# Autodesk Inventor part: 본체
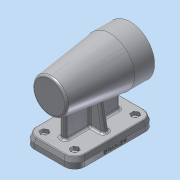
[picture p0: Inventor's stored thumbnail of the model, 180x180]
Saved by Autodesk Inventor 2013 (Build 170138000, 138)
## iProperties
Created: 2017-01
Part Number: 본체
Material: 알루미늄 6061
Document SubType Name: Modeling
Designer: dgall
Density: 1 g/cm^3
Author: dgall
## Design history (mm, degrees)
sketch "스케치1"
  geometry: C1 r 34 at (0, 0); 1 further point
  constraints: 1 centre point, 1 coincident
  dimensions: "d0" = 68 diameter of C1
extrude "돌출1" new body sketch "스케치1" distance "d2" = 28; taper "d3" = 0 deg
sketch "스케치2"
  geometry: C1 r 34 at (0, 0) reference; C2 r 34 at (0, 0)
  constraints: 1 centre point, 1 coincident, 1 concentric
extrude "돌출2" join sketch "스케치2" distance "d4" = 84; taper "d5" = -7 deg
node "작업 평면1"
sketch "스케치3"
  geometry: L1 (-35, -84)-(35, -84); L2 (35, -84)-(35, 28); L3 (35, 28)-(-35, 28); L4 (-35, 28)-(-35, -84); L5 (-34, 0)-(-23.686, -84) reference; L6 (-34, 0)-(-34, 28) reference; L7 (-30.562, -28)-(-14.801, -28); L8 (23.686, -84)-(-23.686, -84) reference; L9 (0, -84)-(0, -66.42); 1 further point
  constraints: 12 end point, 3 perpendicular, 2 parallel, 1 horizontal, 1 midpoint, 1 point on line
  dimensions: "d7" = 56 vertical distance of L7.start L5.end; "d8" = 56 distance between parallel lines of L1 L7; "d9" = 56 distance between parallel lines of L3 L7; "d10" = 35 distance between parallel lines of L4 L9; "d11" = 35 distance between parallel lines of L9 L2
extrude "돌출3" join sketch "스케치3" distance "d12" = 7; taper "d13" = 0 deg
sketch "스케치4"
  geometry: L1 (-35, -84)-(35, -84) reference; L2 (35, -84)-(35, 28) reference; L3 (35, 28)-(-35, 28) reference; L4 (-35, -84)-(35, -84); L5 (35, -84)-(35, 28); L6 (35, 28)-(-35, 28); L7 (-35, 28)-(-35, -84); 1 further point
  constraints: 8 end point, 2 parallel, 1 horizontal, 1 perpendicular, 1 point on line
  dimensions: "d14" = 0 distance between parallel lines of L3 L6
extrude "돌출4" join sketch "스케치4" distance "d15" = 7; taper "d16" = -15 deg
node "작업 평면2"
sketch "스케치5"
  geometry: L1 (-82.124, -60)-(26.124, -60) reference; L2 (0, -34)-(-84, -23.686) reference; L3 (0, -34)-(28, -34) reference; L4 (-66, -25.896)-(-66, -60); L5 (-84, -74)-(-84, -67) reference; L6 (10, -34)-(10, -60); L7 (28, -74)-(28, -67) reference; L8 (-66, -60)-(10, -60); L9 (-66, -25.896)-(0, -34); L10 (10, -34)-(0, -34); 1 further point
  constraints: 10 end point, 4 point on line, 3 collinear, 2 perpendicular
  dimensions: "d18" = 18 distance from line of L4.end L5; "d19" = 18 distance from line of L6.end L7
extrude "돌출5" join sketch "스케치5" stored distance "d20" = 8; taper "d21" = 0 deg
node "작업 평면3"
sketch "스케치6"
  geometry: L1 (-33.124, -60)-(33.124, -60) reference; L2 (-23, -60)-(-17.555, -29.118); L3 (-35, -74)-(-35, -67) reference; 2 further points
  constraints: 2 end point, 1 point on line
  dimensions: "d23" = 12 distance from line of L2.start L3; "d24" = 100 deg angle of L1 L2
sketch "스케치7"
  geometry: C1 r 34 at (0, 0) reference; C2 r 21 at (0, 0)
  constraints: 1 centre point, 1 coincident
  dimensions: "d25" = 42 diameter of C2
extrude "돌출6" cut sketch "스케치7" distance "d27" = 15; taper "d28" = 0 deg
sketch "스케치8"
  geometry: C1 r 21 at (0, 0) reference; C2 r 24 at (0, 0)
  constraints: 1 centre point, 1 coincident
  dimensions: "d29" = 48 diameter of C2
extrude "돌출7" cut sketch "스케치8" distance "d31" = 54; taper "d32" = 0 deg
sketch "스케치9"
  geometry: C1 r 21 at (0, 0) reference
extrude "돌출8" cut sketch "스케치9" distance "d33" = 54; taper "d34" = 0 deg
sketch "스케치10"
  geometry: C1 r 24 at (0, 0) reference; C2 r 21 at (0, 0)
  constraints: 1 centre point, 1 coincident
  dimensions: "d35" = 42 diameter of C2
extrude "돌출9" cut sketch "스케치10" distance "d37" = 12; taper "d38" = 0 deg
sketch "스케치11"
  geometry: C1 r 21 at (0, 0) reference; C2 r 17.5 at (0, 0)
  constraints: 1 centre point, 1 coincident
  dimensions: "d39" = 35 diameter of C2
extrude "돌출10" cut sketch "스케치11" distance "d41" = 18; taper "d42" = 0 deg
sketch "스케치12"
  geometry: C1 r 17.5 at (0, 0) reference; C2 r 16 at (0, 0)
  constraints: 1 centre point, 1 coincident
  dimensions: "d43" = 32 diameter of C2
extrude "돌출11" cut sketch "스케치12" distance "d45" = 4; taper "d46" = 0 deg
sketch "스케치13"
  geometry: C1 r 16 at (0, 0) reference; C2 r 10.5 at (0, 0)
  constraints: 1 centre point, 1 coincident
  dimensions: "d47" = 21 diameter of C2
extrude "돌출12" cut sketch "스케치13" distance "d49" = 3; taper "d50" = 0 deg
sketch "스케치14"
  geometry: C1 r 21 at (0, 0) reference; C2 r 34 at (0, 0) reference; C3 r 2 at (0, -26); C4 r 2 at (26, 0); C5 r 2 at (0, 26); C6 r 2 at (-26, 0); A1 r 26 centre (0, 0) between (0, -26) and (26, 0)
  constraints: 5 centre point, 4 point on circle, 2 horizontal alignment, 2 vertical alignment, 1 coincident
  dimensions: "d51" = 52 diameter of A1; "d53" = 4 diameter of C3; "d54" = 4 diameter of C4; "d55" = 4 diameter of C5; "d56" = 4 diameter of C6
hole "구멍1" sketch "스케치14" at (0, -26), (26, 0), (0, 26), (-26, 0) diameter "d57" = 3.242; stored, may be unused: countersink angle "d61" = 82 deg, drill point angle "d63" = 118 deg; dims "d58" = 8, "d59" = 3.023, "d60" = 2, "d62" = 11
node "작업 평면4"
sketch "스케치15"
  geometry: L1 (-33.124, -60)-(33.124, -60) reference; L2 (-23, -60)-(-15.632, -18.211); L3 (-35, -74)-(-35, -67) reference; L4 (35, -74)-(35, -67) reference; C1 r 21 at (0, 0) reference; C2 r 21 at (0, 0) reference; 2 further points
  constraints: 2 end point, 1 point on line, 2 other
  dimensions: "d65" = 12 distance from line of L2.start L3; "d67" = 100 deg angle of L1 L2
feature "리브1" sketch "스케치15" dims "d68" = 1, "d69" = 8, "d70" = 0, "d71" = 0, "d72" = 1, "d73" = 1
sketch "스케치16"
  geometry: L1 (-33.124, -60)-(33.124, -60) reference; L2 (15.632, -18.211)-(23, -60); L3 (35, -74)-(35, -67) reference; 2 further points
  constraints: 2 end point, 1 point on line, 2 other
  dimensions: "d74" = 12 distance from line of L2.end L3; "d75" = 100 deg angle of L1 L2
feature "리브2" sketch "스케치16" dims "d76" = 1, "d77" = 8, "d78" = 0, "d79" = 0, "d80" = 1, "d81" = 1
chamfer "모따기1" distance "d82" = 1; stored, may be unused: second distance "d83" = 2, angle "d84" = 45 deg
fillet "모깎기1" dims "d85" = 3
fillet "모깎기2" dims "d86" = 3
fillet "모깎기3" dims "d87" = 3
sketch "스케치19"
  geometry: L1 (-33.124, -82.124)-(-33.124, 26.124) reference; L2 (33.124, -82.124)-(-33.124, -82.124) reference; L3 (7, -21)-(7, 7) reference; L4 (-33.124, -28)-(-27.927, -28); L5 (0, -82.124)-(0, -76.165); L6 (-16, -67.113)-(-16, -72.887); L7 (-16, -72.887)-(-21, -75.774); L8 (-21, -75.774)-(-26, -72.887); L9 (-26, -72.887)-(-26, -67.113); L10 (-26, -67.113)-(-21, -64.226); L11 (-21, -64.226)-(-16, -67.113); L12 (26, -67.113)-(26, -72.887); L13 (26, -72.887)-(21, -75.774); L14 (21, -75.774)-(16, -72.887); L15 (16, -72.887)-(16, -67.113); L16 (16, -67.113)-(21, -64.226); L17 (21, -64.226)-(26, -67.113); L18 (-16, 16.887)-(-16, 11.113); L19 (-16, 11.113)-(-21, 8.226); L20 (-21, 8.226)-(-26, 11.113); L21 (-26, 11.113)-(-26, 16.887); L22 (-26, 16.887)-(-21, 19.774); L23 (-21, 19.774)-(-16, 16.887); L24 (26, 16.887)-(26, 11.113); L25 (26, 11.113)-(21, 8.226); L26 (21, 8.226)-(16, 11.113); L27 (16, 11.113)-(16, 16.887); L28 (16, 16.887)-(21, 19.774); L29 (21, 19.774)-(26, 16.887); C1 r 5 at (-21, -70); C2 r 5 at (21, -70); C3 r 5 at (-21, 14); C4 r 5 at (21, 14); 5 further points
  constraints: 52 end point, 11 tangent, 4 centre point, 2 midpoint, 2 perpendicular, 52 other
  dimensions: "d102" = 42 distance from line of C1.centre L4; "d104" = 42 distance from line of C3.centre L4; "d105" = 42 distance from line of C2.centre L4; "d106" = 42 distance from line of C4.centre L4; "d107" = 21 distance from line of C1.centre L5; "d108" = 21 distance from line of L5 C2.centre; "d109" = 21 horizontal distance of C3.centre L5.end; "d110" = 21 distance from line of C4.centre L5; "d111" = 10 diameter of C1; "d112" = 10 diameter of C3; "d113" = 10 diameter of C2; "d114" = 10 diameter of C4; "d115" = 0 distance of C1.centre point (-21, -70); "d116" = 0 horizontal distance of L8.end L9.end; "d117" = 0 horizontal distance of L14.end L15.end; "d118" = 0 horizontal distance of L21.end L20.end; "d119" = 0 horizontal distance of L26.end L27.end
extrude "돌출14" cut sketch "스케치19" distance "d120" = 5; taper "d121" = 0 deg
fillet "모깎기4" dims "d122" = 3
fillet "모깎기5" dims "d123" = 0.3
fillet "모깎기6" dims "d124" = 2
sketch "스케치20"
  geometry: L1 (-26, -72.887)-(-26, -67.113) reference; L2 (-26, -70)-(-21, -70); C1 r 2.5 at (-21, -70); 2 further points
  constraints: 2 end point, 1 centre point, 1 coincident, 1 midpoint, 1 perpendicular, 1 vertical alignment
  dimensions: "d125" = 5 diameter of C1
extrude "돌출15" cut sketch "스케치20" stored distance "d127" = 5; taper "d128" = 0 deg
sketch "스케치21"
  geometry: L1 (16, -72.887)-(16, -67.113) reference; L2 (16, -70)-(18.133, -70); C1 r 2.5 at (21, -70); 2 further points
  constraints: 2 end point, 1 centre point, 1 midpoint, 1 perpendicular, 1 vertical alignment
  dimensions: "d129" = 0 distance from line of C1.centre L2; "d131" = 5 diameter of C1
extrude "돌출16" cut sketch "스케치21" stored distance "d132" = 5; taper "d133" = 0 deg
sketch "스케치22"
  geometry: L1 (-26, 11.113)-(-26, 16.887) reference; L2 (-26, 14)-(-24.496, 14); C1 r 2.5 at (-21, 14); 2 further points
  constraints: 2 end point, 1 centre point, 1 midpoint, 1 perpendicular, 1 vertical alignment
  dimensions: "d134" = 0 distance from line of C1.centre L2; "d136" = 5 diameter of C1
extrude "돌출17" cut sketch "스케치22" stored distance "d137" = 5; taper "d138" = 0 deg
sketch "스케치23"
  geometry: L1 (16, 11.113)-(16, 16.887) reference; L2 (16, 14)-(26, 14); C1 r 2.5 at (21, 14); 3 further points
  constraints: 2 end point, 2 midpoint, 1 centre point, 1 coincident, 1 perpendicular, 1 vertical alignment
  dimensions: "d139" = 5 diameter of C1
extrude "돌출18" cut sketch "스케치23" stored distance "d141" = 5; taper "d142" = 0 deg
fillet "모깎기7" dims "d143" = 14
fillet "모깎기8" dims "d144" = 1
node "작업 평면5"
sketch "스케치24"
  geometry: L1 (-53.253, -67.598)-(-2.747, -67.598); L2 (-2.747, -67.598)-(-2.747, -72.402); L3 (-2.747, -72.402)-(-53.253, -72.402); L4 (-53.253, -72.402)-(-53.253, -67.598); L5 (-53.253, -70)-(-2.747, -70); L6 (-28, -67.598)-(-28, -72.402); L7 (-70, -74)-(14, -74) reference; L8 (28, -74)-(28, -67) reference; 1 further point
  constraints: 4 end point, 4 midpoint, 2 other
  dimensions: "d146" = 4 distance from line of L5.start L7; "d147" = 56 distance between parallel lines of L6 L8
feature "엠보싱1" sketch "스케치24" dims "d0" = 68, "d7" = 56, "d8" = 56, "d9" = 56, "d10" = 35, "d11" = 35, "d148" = 0.5, "d149" = 0
node "솔리드1"
node "투영된 루프1"
other parameters: "d6" = -74, "d17" = 0, "d22" = -56, "d64" = -56, "d145" = 64.75
